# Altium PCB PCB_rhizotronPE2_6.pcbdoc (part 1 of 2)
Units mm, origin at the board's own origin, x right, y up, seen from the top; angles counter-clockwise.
Board outline 141.81 x 99.53 mm, 2 copper layers (Top Layer, Bottom Layer); 83 components, 239 nets, 496 pads, 263 vias.
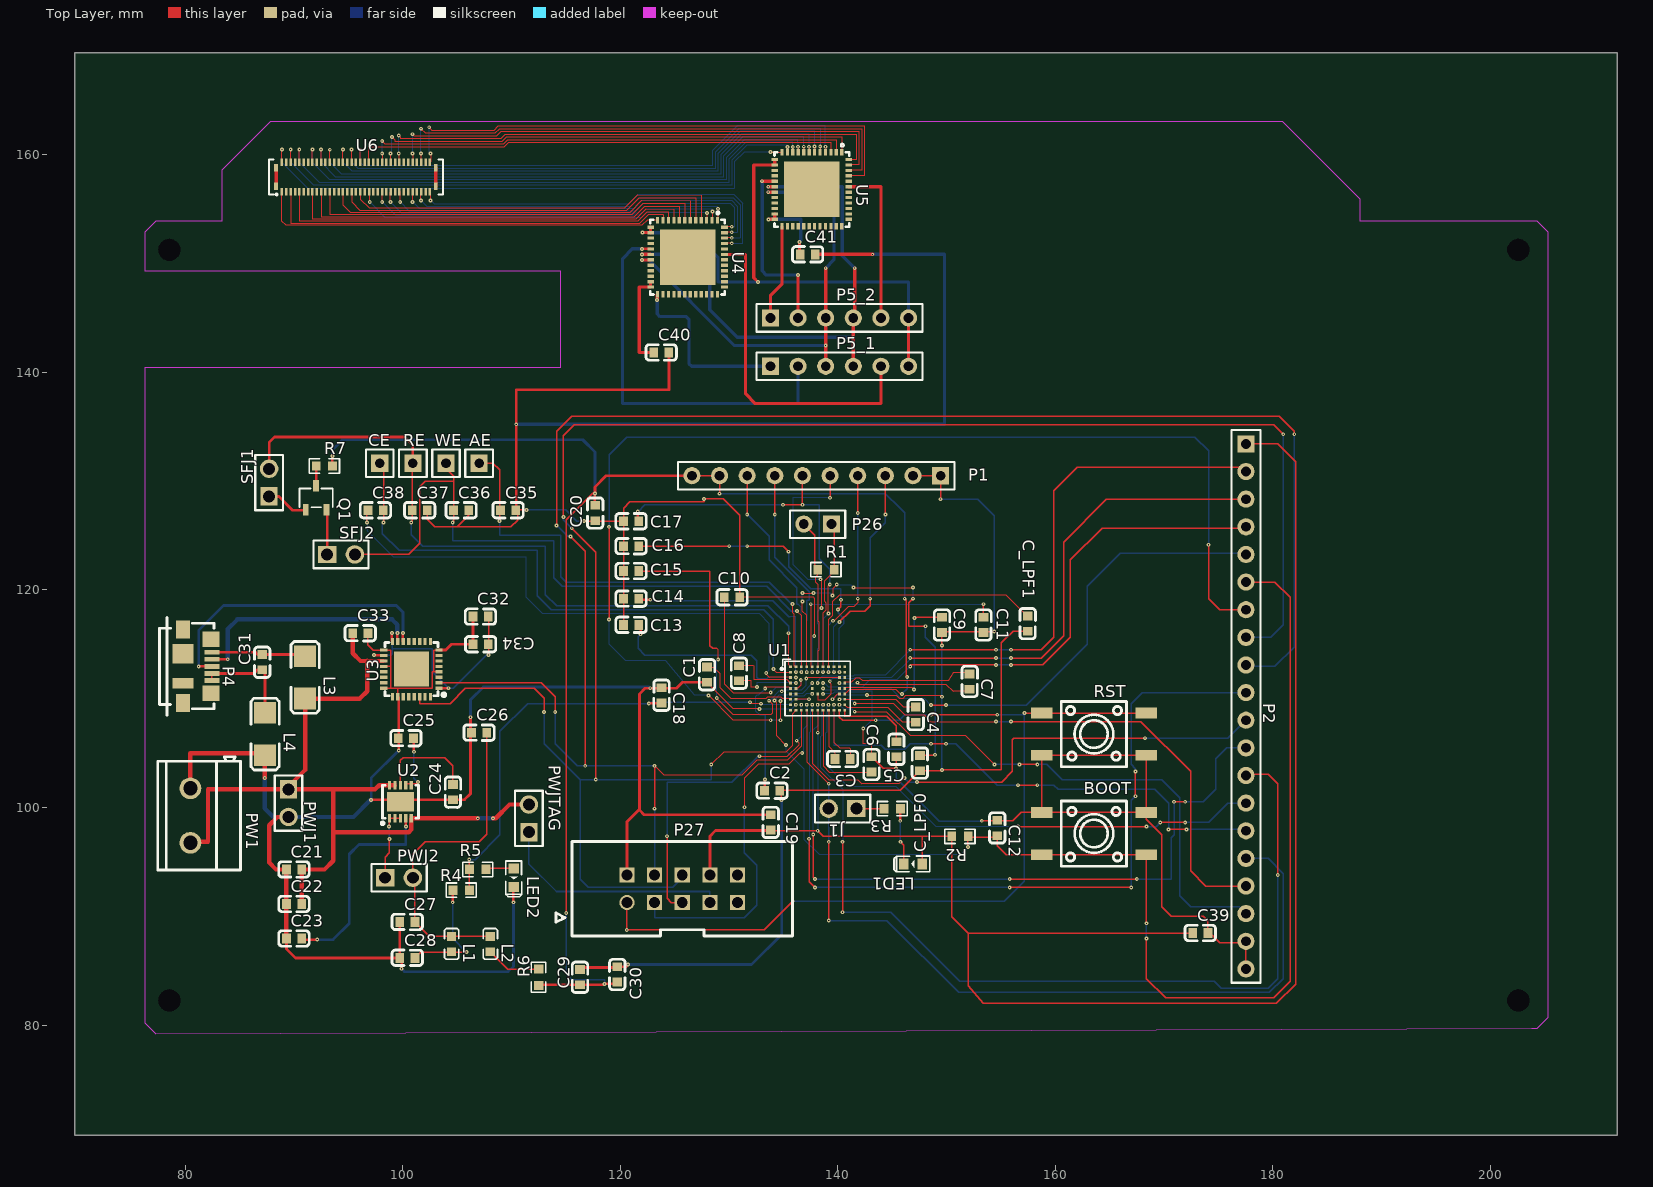
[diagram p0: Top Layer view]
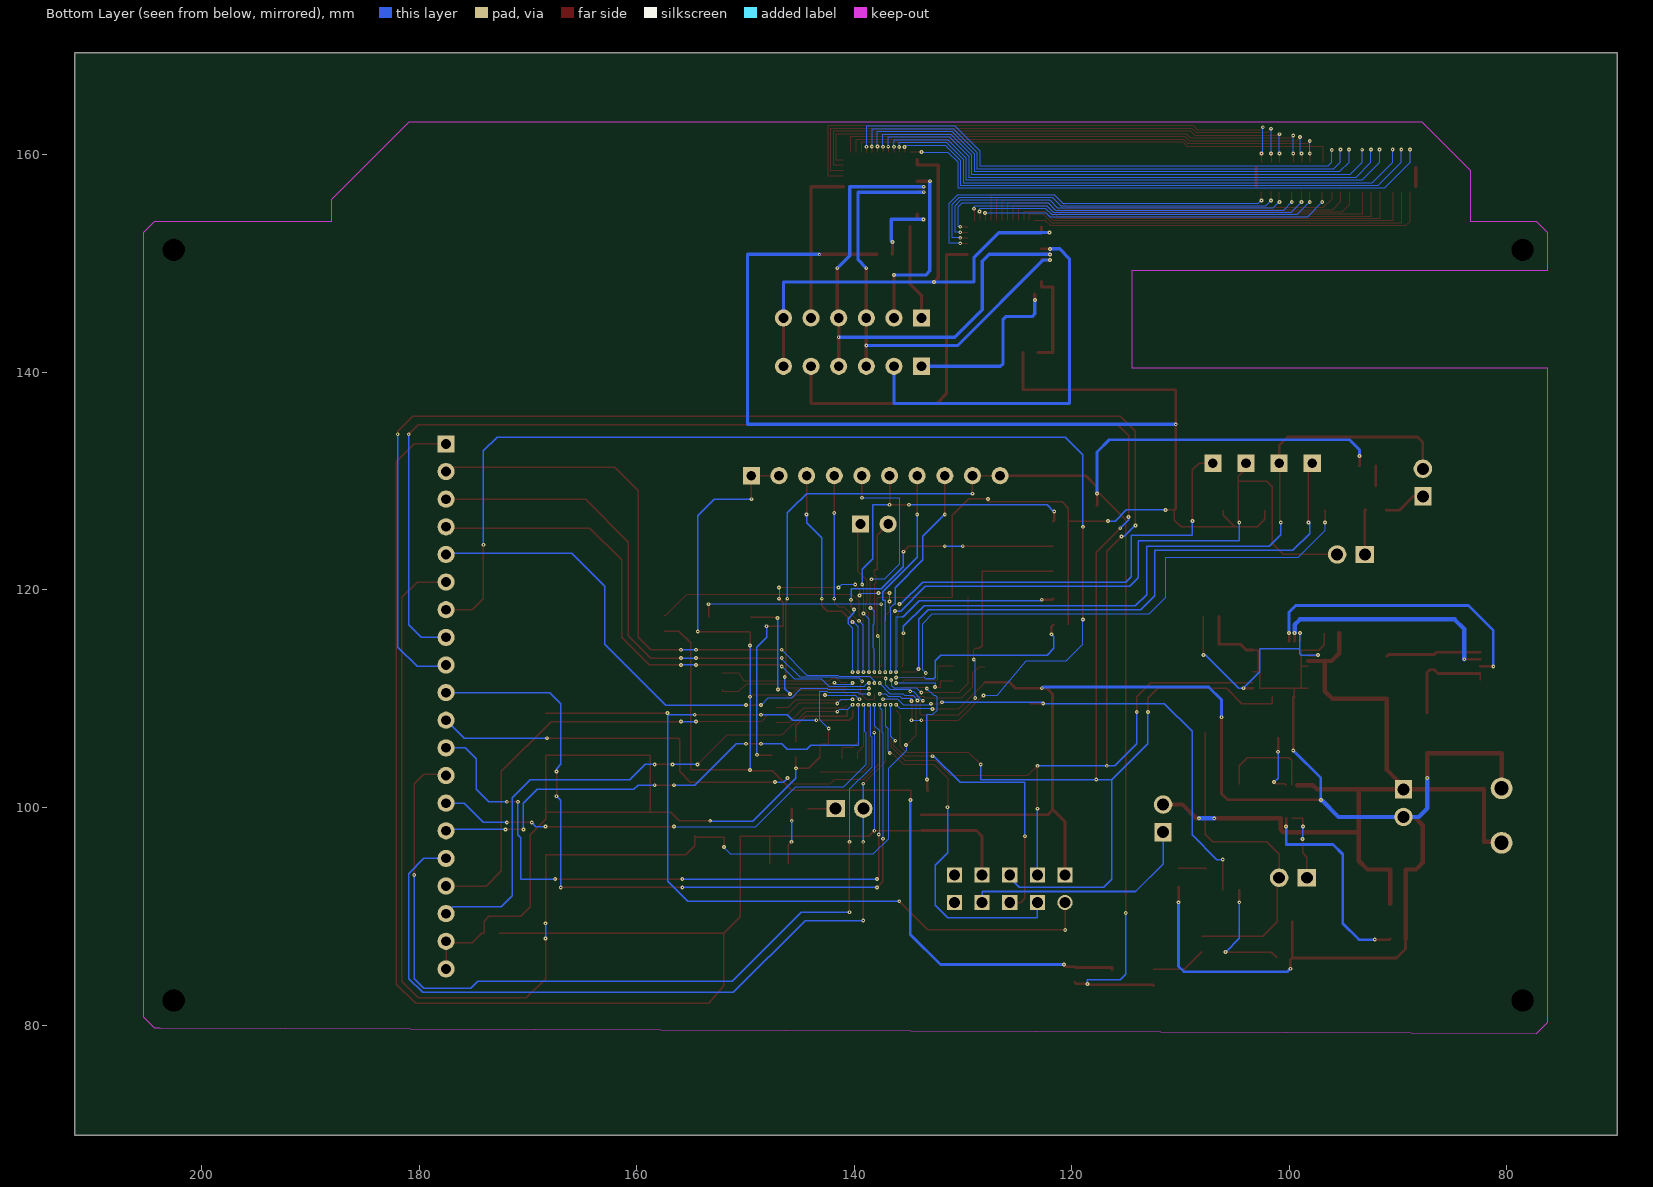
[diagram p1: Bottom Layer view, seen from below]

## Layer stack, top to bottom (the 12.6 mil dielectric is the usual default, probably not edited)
Top Layer: signal copper (thickness not stored)
Dielectric: dielectric 0.32, FR-4, Dk 4.8
Bottom Layer: signal copper (thickness not stored)

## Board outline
211.657,69.85 69.85,69.85 69.85,169.382 211.657,169.382
cut-out: 79.577,82.26 ccw(c78.561,82.26) 77.545,82.26 ccw(c78.561,82.26)
cut-out: 79.577,151.26 ccw(c78.561,151.26) 77.545,151.26 ccw(c78.561,151.26)
cut-out: 203.577,151.26 ccw(c202.561,151.26) 201.545,151.26 ccw(c202.561,151.26)
cut-out: 203.577,82.26 ccw(c202.561,82.26) 201.545,82.26 ccw(c202.561,82.26)

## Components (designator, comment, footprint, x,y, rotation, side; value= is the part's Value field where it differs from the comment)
AE "HDR-M-2.54_1x1" HDR-M-2.54_1X1 107.033,131.639 r270 top
BOOT "K4-6×6_SMD" KEY-SMD_4P-L6.0-W6.0-P3.90-LS10.0 163.548,97.603 r180 top
C1 "0.47uF" C0603 127.988,112.208 r90 top
C2 "0.47uF" C0603 133.957,101.54 r0 top
C3 "0.1uF" C0603 140.434,104.461 r180 top
C4 "0.1uF" C0603 147.165,108.525 r270 top
C5 "0.47uF" C0603 145.387,105.35 r90 top
C6 "0.47uF" C0603 143.101,103.953 r90 top
C7 "0.1uF" C0603 152.118,111.573 r270 top
C8 "0.1uF" C0603 130.909,112.335 r270 top
C9 "0.47uF" C0603 149.578,116.78 r90 top
C10 "0.47uF" C0603 130.274,119.32 r180 top
C11 "4.7uF" C0603 153.388,116.78 r90 top
C12 "0.1uF" C0603 154.658,98.111 r270 top
C13 "0.1uF" C0603 121.003,116.78 r0 top
C14 "0.1uF" C0603 121.003,119.193 r0 top
C15 "0.1uF" C0603 121.003,121.733 r0 top
C16 "0.1uF" C0603 121.003,124.019 r0 top
C17 "0.1uF" C0603 121.003,126.305 r0 top
C18 "0.1uF" C0603 123.797,110.303 r270 top
C19 "0.1uF" C0603 133.83,98.619 r270 top
C20 "0.1uF" C0603 117.701,127.067 r90 top
C21 "0.1uF" C0603 90.015,94.301 r0 top
C22 "10uF" C0603 90.015,91.126 r0 top
C23 "1uF" C0603 90.015,87.951 r0 top
C24 "1uF" C0603 104.62,101.413 r90 top
C25 "1uF" C0603 100.302,106.366 r0 top
C26 "10uF" C0603 107.033,106.874 r0 top
C27 "0.1uF" C0603 100.429,89.475 r0 top
C28 "0.1uF" C0603 100.429,86.173 r0 top
C29 "0.1uF" C0603 116.304,84.395 r90 top
C30 "10uF" C0603 119.733,84.649 r90 top
C31 "0.1uF" C0603 87.094,113.351 r90 top
C32 "0.1uF" C0603 107.16,117.542 r0 top
C33 "0.1uF" C0603 96.111,116.018 r0 top
C34 "0.1uF" C0603 107.16,115.002 r180 top
C35 "0.1uF" C0603 109.7,127.321 r0 top
C36 "0.1uF" C0603 105.382,127.321 r0 top
C37 "0.1uF" C0603 101.572,127.321 r0 top
C38 "0.1uF" C0603 97.508,127.321 r0 top
C39 "0.1uF" C0603 173.327,88.459 r0 top
C40 "0.1uF" C0603 123.773,141.823 r0 top
C41 "0.1uF" C0603 137.235,150.84 r0 top
C_LPF0 "4.7uF" C0603 147.546,104.08 r90 top
C_LPF1 "4.7uF" C0603 157.452,116.907 r90 top
CE "HDR-M-2.54_1x1" HDR-M-2.54_1X1 97.889,131.639 r270 top
J1 "HDR-M-2.54_1x2" HDR-M-2.54_1X2 140.434,99.889 r180 top
L1 "60Ω" L0603 104.493,87.443 r270 top
L2 "60Ω" L0603 108.049,87.443 r270 top
L3 "80Ω" L1806 91.031,111.954 r270 top
L4 "80Ω" L1806 87.348,106.747 r270 top
LED1 "LED-0603_G" LED0603_GREEN 146.911,94.809 r180 top
LED2 "LED-0603_G" LED0603_GREEN 110.208,93.539 r270 top
P1 "HDR-F-2.54_1x10" HDR-F-2.54_1X10 138.021,130.496 r180 top
P2 "HDR-F-2.54_1x20" HDR-F-2.54_1X20 177.518,109.287 r270 top
P4 "Micro B USB 2.0 SMD connector" SD-47346-001 83.157,112.97 r270 top
P5_1 "HDR-F-2.54_1x6" HDR-F-2.54_1X6 138.886,140.553 r0 top
P5_2 "HDR-F-2.54_1x6" HDR-F-2.54_1X6 138.886,144.998 r0 top
P26 "P26" HDR-F-2.54_1X2 138.148,126.051 r180 top
P27 "CONNMOLEX 2X5 Male" JTAG-10PIN-2.54MM-PTH 125.702,92.523 r0 top
PW1 "CONN-TH_2P-P5.00" CONN-TH_2P-P5.00 80.49,99.254 r270 top
PWJ1 "HDR-M-2.54_1x2" HDR-M-2.54_1X2 89.507,100.397 r270 top
PWJ2 "HDR-M-2.54_1x2" HDR-M-2.54_1X2 99.667,93.539 r0 top
PWJTAG "HDR-M-2.54_1x2" HDR-M-2.54_1X2 111.605,99 r90 top
Q1 "MMBFJ177" SOT-23-3_L3.0-W1.7-P0.95-LS2.9-BR 92.047,128.464 r270 top
R1 "200" R0603 138.91,121.86 r0 top
R2 "100K" R0603 151.229,97.349 r180 top
R3 "560" R0603 145.006,99.889 r180 top
R4 "2.2" R0603 105.382,92.396 r180 top
R5 "560" R0603 106.906,94.301 r180 top
R6 "2.2" R0603 112.494,84.395 r90 top
R7 "150K" R0603 92.809,131.385 r0 top
RE "HDR-M-2.54_1x1" HDR-M-2.54_1X1 100.937,131.639 r270 top
RST "K4-6×6_SMD" KEY-SMD_4P-L6.0-W6.0-P3.90-LS10.0 163.548,106.747 r0 top
SFJ1 "HDR-M-2.54_1x2" HDR-M-2.54_1X2 87.729,129.861 r90 top
SFJ2 "HDR-M-2.54_1x2" HDR-M-2.54_1X2 94.333,123.257 r0 top
U1 "ADUCM355BCCZ" lga-72_l6.0-w5.0-tl_aducm355bccz-rl7 138.148,110.938 r0 top
U2 "ADP7158ACPZ-3.3-R7" LFCSP-10_L3.0-W3.0-P0.50-BL-EP 99.794,100.524 r0 top
U3 "FT232RQ" QFN-32_L5.0-W5.0-P0.50-BL-EP 100.81,112.716 r90 top
U4 "ADG731BCPZ" LFCSP-48_L7.0-W7.0-P0.50-TL-EP5.1 126.186,150.586 r270 top
U5 "ADG731BCPZ" LFCSP-48_L7.0-W7.0-P0.50-TL-EP5.1 137.616,156.809 r270 top
U6 "DF40GB-70DP-0.4V(51)" "HIROSE DF40GB-70DP-0.4V(51)" 95.706,157.952 r0 top
WE "HDR-M-2.54_1x1" HDR-M-2.54_1X1 103.985,131.639 r270 top

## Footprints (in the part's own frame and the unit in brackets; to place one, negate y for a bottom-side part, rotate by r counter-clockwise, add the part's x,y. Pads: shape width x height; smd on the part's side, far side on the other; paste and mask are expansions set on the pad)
C0603 [mm]
  rect 0.8x0.9 smd paste+0 mask+0.051: 1(-0.7,0) 2(0.7,0)
  silkscreen extent -1.41,-0.71 1.39,0.72
CONN-TH_2P-P5.00 [mm]
  round 2 hole 1.3 paste+0 mask+0.051: 1(-2.504,0) 2(2.504,0)
  silkscreen extent -5.4,-3 5,4.6
HDR-F-2.54_1X2 [mil]
  rect 62x62 hole 35 paste+0 mask+2: 1(-50,0)
  round 62 hole 35 paste+0 mask+2: 2(50,0)
  silkscreen extent -100,-49 100,50
HDR-F-2.54_1X6 [mil]
  rect 62x62 hole 35 paste+0 mask+2: 1(-200,0)
  round 62 hole 35 paste+0 mask+2: 2(-100,0) 3(0,0) 4(100,0) 5(200,0) 6(300,0)
  silkscreen extent -250,-50 350,50
HDR-F-2.54_1X10 [mil]
  rect 62x62 hole 35 paste+0 mask+2: 1(-450,0)
  round 62 hole 35 paste+0 mask+2: 2(-350,0) 3(-250,0) 4(-150,0) 5(-50,0) 6(50,0) 7(150,0) 8(250,0) 9(350,0) 10(450,0)
  silkscreen extent -500,-50 500,50
HDR-F-2.54_1X20 [mil]
  rect 62x62 hole 35 paste+0 mask+2: 1(-950,0)
  round 62 hole 35 paste+0 mask+2: 2(-850,0) 3(-750,0) 4(-650,0) 5(-550,0) 6(-450,0) 7(-350,0) 8(-250,0) 9(-150,0) 10(-50,0) 11(50,0) 12(150,0) 13(250,0) 14(350,0) 15(450,0) 16(550,0) 17(650,0) 18(750,0) 19(850,0) 20(950,0)
  silkscreen extent -1000,-53 1000,53
HDR-M-2.54_1X1 [mil]
  rect 62x62 hole 35 paste+0 mask+2: 1(0,0)
  silkscreen extent -50,-50 50,50
HDR-M-2.54_1X2 [mm]
  rect 1.7x1.575 hole 1.1 paste+0 mask+0.051: 1(-1.27,0)
  round 1.7 hole 1.1 paste+0 mask+0.051: 2(1.27,0)
  silkscreen extent -2.54,-1.27 2.54,1.27
"HIROSE DF40GB-70DP-0.4V(51)" [mm]
  rect 0.23x0.66 smd paste+0 mask+0.051: 1(-6.8,-1.355) 2(-6.8,1.355) 3(-6.401,-1.355) 4(-6.4,1.355) 5(-6,-1.355) 6(-6,1.355) 7(-5.6,-1.355) 8(-5.6,1.355) 9(-5.2,-1.355) 10(-5.2,1.355) 11(-4.8,-1.355) 12(-4.8,1.355) 13(-4.4,-1.355) 14(-4.4,1.355) 15(-4,-1.355) 16(-4,1.355) 17(-3.6,-1.355) 18(-3.6,1.355) 19(-3.2,-1.355) 20(-3.2,1.355) 21(-2.8,-1.355) 22(-2.8,1.355) 23(-2.4,-1.355) 24(-2.4,1.355) 25(-2,-1.355) 26(-2,1.355) 27(-1.6,-1.355) 28(-1.6,1.355) 29(-1.2,-1.355) 30(-1.2,1.355) 31(-0.8,-1.355) 32(-0.8,1.355) 33(-0.4,-1.355) 34(-0.4,1.355) 35(0,-1.355) 36(0,1.355) 37(0.4,-1.355) 38(0.4,1.355) 39(0.8,-1.355) 40(0.8,1.355) 41(1.2,-1.355) 42(1.2,1.355) 43(1.6,-1.355) 44(1.6,1.355) 45(2,-1.355) 46(2,1.355) 47(2.4,-1.355) 48(2.4,1.355) 49(2.8,-1.355) 50(2.8,1.355) 51(3.2,-1.355) 52(3.2,1.355) 53(3.6,-1.355) 54(3.6,1.355) 55(4,-1.355) 56(4,1.355) 57(4.4,-1.355) 58(4.4,1.355) 59(4.8,-1.355) 60(4.8,1.355) 61(5.2,-1.355) 62(5.2,1.355) 63(5.6,-1.355) 64(5.6,1.355) 65(6,-1.355) 66(6,1.355) 67(6.4,-1.355) 68(6.4,1.355) 69(6.8,-1.355) 70(6.8,1.355)
  rect 0.35x0.7 smd paste+0 mask+0.051: 71(7.335,-0.86) 72(7.335,0.86) 73(-7.335,-0.86) SHLD(-7.335,0.86)
  silkscreen extent -8,-1.7 8,1.6
JTAG-10PIN-2.54MM-PTH [mm]
  round 1.4 hole 1.001 paste+0 mask+0.051: 1(-5.08,-1.27)
  rect 1.4x1.4 hole 1.001 paste+0 mask+0.051: 2(-5.08,1.27) 3(-2.54,-1.27) 4(-2.54,1.27) 5(0,-1.27) 6(0,1.27) 7(2.54,-1.27) 8(2.54,1.27) 9(5.08,-1.27) 10(5.08,1.27)
  silkscreen extent -11.61,-4.34 10.13,4.34
KEY-SMD_4P-L6.0-W6.0-P3.90-LS10.0 [mm]
  rect 2x1 smd paste+0 mask+0.051: 1(-4.8,1.95) 2(4.8,1.95) 3(-4.8,-1.95) 4(4.8,-1.95)
  silkscreen extent -3,-3 3,3
L0603 [mm]
  rect 0.8x0.864 smd paste-100 mask+0.051: 1(-0.7,0) 2(0.7,0)
  silkscreen extent -1.42,-0.65 1.41,0.67
L1806 [mm]
  rect 2x2 smd paste+0 mask+0.051: 1(-1.95,0) 2(1.95,0)
  silkscreen extent -3.3,-1.3 3.3,1.3
LED0603_GREEN [mm]
  rect 0.9x1 smd paste+0 mask+0.051: 1(-0.85,0) 2(0.85,0)
  silkscreen extent -1.54,-0.73 1.75,0.73
LFCSP-10_L3.0-W3.0-P0.50-BL-EP [mm]
  rect 0.3x0.8 smd paste+0 mask+0.051: 1(-1,-1.524) 2(-0.5,-1.524) 3(0,-1.524) 4(0.5,-1.524) 5(1,-1.524) 6(1,1.524) 7(0.5,1.524) 8(0,1.524) 9(-0.5,1.524) 10(-1,1.524)
  rect 2.5x1.75 smd paste+0 mask+0.051: 11(0,0)
  silkscreen extent -1.77,-2.11 1.65,1.52
LFCSP-48_L7.0-W7.0-P0.50-TL-EP5.1 [mm]
  rect 0.6x0.3 smd paste-100 mask+0.051: 1(-3.4,2.75) 2(-3.4,2.25) 3(-3.4,1.75) 4(-3.4,1.25) 5(-3.4,0.75) 6(-3.4,0.25) 7(-3.4,-0.25) 8(-3.4,-0.75) 9(-3.4,-1.25) 10(-3.4,-1.75) 11(-3.4,-2.25) 12(-3.4,-2.75) 25(3.4,-2.75) 26(3.4,-2.25) 27(3.4,-1.75) 28(3.4,-1.25) 29(3.4,-0.75) 30(3.4,-0.25) 31(3.4,0.25) 32(3.4,0.75) 33(3.4,1.25) 34(3.4,1.75) 35(3.4,2.25) 36(3.4,2.75)
  rect 0.3x0.6 smd paste-100 mask+0.051: 13(-2.75,-3.4) 14(-2.25,-3.4) 15(-1.75,-3.4) 16(-1.25,-3.4) 17(-0.75,-3.4) 18(-0.25,-3.4) 19(0.25,-3.4) 20(0.75,-3.4) 21(1.25,-3.4) 22(1.75,-3.4) 23(2.25,-3.4) 24(2.75,-3.4) 37(2.75,3.4) 38(2.25,3.4) 39(1.75,3.4) 40(1.25,3.4) 41(0.75,3.4) 42(0.25,3.4) 43(-0.25,3.4) 44(-0.75,3.4) 45(-1.25,3.4) 46(-1.75,3.4) 47(-2.25,3.4) 48(-2.75,3.4)
  rect 5.1x5.1 smd paste-100 mask+0.051: 49(0,0)
  silkscreen extent -4.19,-3.43 3.43,3.43
lga-72_l6.0-w5.0-tl_aducm355bccz-rl7 [mm]
  rect 0.25x0.25 smd paste+0 mask+0.051: A1(-2.5,2) A2(-2,2) A3(-1.5,2) A4(-1,2) A5(-0.5,2) A6(0,2) A7(0.5,2) A8(1,2) A9(1.5,2) A10(2,2) A11(2.5,2) B1(-2.5,1.5) B11(2.5,1.5) C1(-2.5,1) C10(2,1) C11(2.5,1) D1(-2.5,0.5) D11(2.5,0.5) E1(-2.5,0) E2(-2,0) E5(-0.5,0) E10(2,0) E11(2.5,0) F1(-2.5,-0.5) F2(-2,-0.5) F6(0,-0.5) F10(2,-0.5) F11(2.5,-0.5) G1(-2.5,-1) G2(-2,-1) G11(2.5,-1) H1(-2.5,-1.5) H11(2.5,-1.5) J1(-2.5,-2) J2(-2,-2) J3(-1.5,-2) J4(-1,-2) J5(-0.5,-2) J6(0,-2) J7(0.5,-2) J8(1,-2) J9(1.5,-2) J10(2,-2) J11(2.5,-2)
  round 0.35 hole 0.1 paste+0 mask+0.051: B2(-2,1.5) B3(-1.5,1.5) B4(-1,1.5) B5(-0.5,1.5) B6(0,1.5) B7(0.5,1.5) B8(1,1.5) B9(1.5,1.5) B10(2,1.5) C2(-2,1) D2(-2,0.5) D5(-0.5,0.5) D6(0,0.5) D7(0.5,0.5) D10(2,0.5) E7(0.5,0) F5(-0.5,-0.5) F7(0.5,-0.5) G10(2,-1) H2(-2,-1.5) H3(-1.5,-1.5) H4(-1,-1.5) H5(-0.5,-1.5) H6(0,-1.5) H7(0.5,-1.5) H8(1,-1.5) H9(1.5,-1.5) H10(2,-1.5)
  silkscreen extent -3.4,-2.5 3,2.7
QFN-32_L5.0-W5.0-P0.50-BL-EP [mil]
  rect 11.8x26 smd paste-3937 mask+1.97: 1(-68.9,-100) 2(-49.21,-100) 3(-29.53,-100) 4(-9.84,-100) 5(9.84,-100) 6(29.53,-100) 7(49.21,-100) 8(68.9,-100) 17(68.9,100) 18(49.21,100) 19(29.53,100) 20(9.84,100) 21(-9.84,100) 22(-29.53,100) 23(-49.21,100) 24(-68.9,100)
  rect 26x11.8 smd paste-3937 mask+1.97: 9(100,-68.9) 10(100,-49.21) 11(100,-29.53) 12(100,-9.84) 13(100,9.84) 14(100,29.53) 15(100,49.21) 16(100,68.9) 25(-100,68.9) 26(-100,49.21) 27(-100,29.53) 28(-100,9.84) 29(-100,-9.84) 30(-100,-29.53) 31(-100,-49.21) 32(-100,-68.9)
  rect 126x126 smd paste-3937 mask+1.97: 33(0,0)
  silkscreen extent -99,-123 96,96
R0603 [mm]
  rect 0.806x0.864 smd paste-100 mask+0.051: 1(-0.753,0) 2(0.753,0)
  silkscreen extent -1.39,-0.66 1.39,0.66
SD-47346-001 [mm]
  rect 0.45x1.38 smd paste+0 mask+0.102: 1(-1.3,-0.69) 2(-0.65,-0.69) 3(0,-0.69) 4(0.65,-0.69) 5(1.3,-0.69)
  rect 1.425x1.55 smd paste+0 mask+0.102: 6(-2.488,-0.775) GND(2.488,-0.775)
  rect 1.65x1.3 smd paste+0 mask+0.102: 7(-3.375,-3.35) 10(3.375,-3.35)
  rect 1.8x1.9 smd paste+0 mask+0.102: 8(-1.15,-3.35)
  rect 1x1.9 smd paste+0 mask+0.102: 9(1.55,-3.35)
  silkscreen extent -4.49,-5.5 4.49,-0.5
SOT-23-3_L3.0-W1.7-P0.95-LS2.9-BR [mm]
  rect 1.037x0.532 smd paste+0 mask+0.051: 1(1.101,-0.95) 2(1.101,0.95) 3(-1.101,0)
  silkscreen extent -0.86,-1.53 0.86,1.53

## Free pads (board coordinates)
  round 0.225 hole 0.1 paste+0 mask+0.051: 1(143.204,150.84)
  round 0.325 hole 0.1 paste+0 mask+0.051: 24(133.679,109.819)

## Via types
v1: diameter 0.35, hole 0.1, Top Layer to Bottom Layer, 263 vias

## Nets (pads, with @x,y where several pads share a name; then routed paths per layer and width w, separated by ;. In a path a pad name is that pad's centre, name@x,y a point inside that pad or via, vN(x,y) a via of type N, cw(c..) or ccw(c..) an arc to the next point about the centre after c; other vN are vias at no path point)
3V3VOUT: C32.2 C34.1 U3.1 U3.16 U3.18 | length 22.7
  Top Layer w0.125: C32.2@107.86,117.542 107.898,117.504 v1(107.898,114.01)
  Top Layer w0.225: v1(97.357,114.01) 98.226,114.01 U3.18@98.27,113.966 ; v1(99.008,116.042) 99.008,115.308 U3.16@99.06,115.256 ; U3.1@103.35,110.966 103.354,110.962 v1(104.215,110.962)
  Bottom Layer w0.125: v1(97.357,114.01) 98.907,114.01 99.032,114.135 99.032,114.596 ; v1(99.008,116.042) 99.032,116.018 99.032,114.596 ; v1(107.898,114.01) 107.692,114.01 104.644,110.962 v1(104.215,110.962) 102.715,112.462 102.715,114.596 99.032,114.596
5VUSB: C21.2 C22.2 C33.1 L3.2 PW1.2 PWJ1.1 PWJTAG.2 U2.5 U2.9 U2.10 U3.19 | length 79.2
  Top Layer w0.4: PW1.2@80.49,96.749 80.581,96.841 82.105,96.841 82.105,101.667 PWJ1.1@89.507,101.667 89.507,101.921 91.031,103.445 L3.2@91.031,110.004 96.065,110.003 96.746,110.684 96.746,112.97 96.746,113.478 U3.19@98.27,113.465 ; PWJ1.1@89.507,101.667 93.612,101.666 ; C22.2@90.715,91.126 C21.2@90.715,94.301 92.809,94.301 93.612,95.104 93.612,97.73 ; C33.1@95.411,116.018 95.41,114.174 96.121,113.465 96.746,113.465 ; U2.10@98.794,102.048 U2.9@99.294,102.048 ; U2.10@98.795,102.047 97.84,102.047 97.459,101.666 93.612,101.666 ; v1(106.906,99) U2.5@100.794,99 100.795,97.969 100.556,97.73 93.612,97.73 ; v1(108.303,99) 108.557,99 109.827,100.27 PWJTAG.2@111.605,100.27 ; 93.612,97.73 93.612,101.666
  Bottom Layer w0.4: v1(106.906,99) v1(108.303,99)
AFEDIE_GPIO0: P2.17 U1.G10 | length 49.8
  Top Layer w0.1: v1@141.553,109.565 145.109,109.565 146.149,108.525 147.927,108.525 148.562,107.89 v1(154.531,107.89)
  Top Layer w0.125: v1(155.928,107.89) 167.866,107.89 172.438,103.318 172.438,94.174 173.835,92.777 P2.17@177.518,92.777
  Bottom Layer w0.1: U1.G10@140.148,109.938 141.18,109.938 v1@141.553,109.565
  Bottom Layer w0.125: v1(154.531,107.89) v1(155.928,107.89)
  other v1: 141.553,109.565
AFEDIE_GPIO1: P2.18 U1.H10 | length 50.6
  Top Layer w0.1: v1@141.553,108.803 144.474,108.803 146.657,106.62 151.737,106.62 v1(154.404,103.953)
  Top Layer w0.125: v1(156.69,103.953) v1(158.341,103.953)
  Bottom Layer w0.1: U1.H10@140.148,109.438 140.581,109.006 141.35,109.006 v1@141.553,108.803
  Bottom Layer w0.125: v1(154.404,103.953) v1(156.69,103.953) ; v1(158.341,103.953) 159.23,103.953 160.627,102.556 169.771,102.556 171.422,100.905 171.422,91.888 172.438,90.872 176.883,90.872 P2.18@177.518,90.237
  other v1: 141.553,108.803
AGND: C2.2 C9.1 C10.1 C11.1 C13.1 C14.1 C15.1 C16.1 C17.1 C20.1 C29.2 C30.2 C35.2 C36.2 C37.2 C40.2 C41.2 C_LPF0.1 C_LPF1.1 P1.1 P1.2 pad.1 U1.B5 U1.F10 | length 280.7
  Top Layer w0.1: C10.1@130.974,119.32 137.767,119.32 137.894,119.193 137.894,115.822 v1(137.837,115.764) ; v1(139.521,109.946) 140.013,110.438 U1.F10@140.148,110.438 ; v1(142.696,110.327) 142.72,110.303 145.387,110.303 145.641,110.049 146.001,110.049 146.256,110.303 149.578,110.303 v1(149.578,110.176)
  Top Layer w0.125: C37.2@102.272,127.321 102.272,126.494 102.969,125.797 105.001,125.797 ; C36.2@106.082,127.321 106.082,126.878 105.001,125.797 ; v1(111.393,127.345) 110.566,127.345 110.566,126.409 109.954,125.797 105.001,125.797 ; v1(116.661,126.329) 116.685,126.305 C17.1@120.303,126.305 ; C13.1@120.303,116.78 C14.1@120.303,119.193 C15.1@120.303,121.733 C16.1@120.303,124.019 C17.1@120.303,126.305 ; C10.1@130.974,119.32 130.974,126.875 129.488,128.361 v1(127.71,128.361) 127.71,128.083 120.876,128.083 120.303,127.51 C17.1@120.303,126.305 ; v1@134.822,100.675 134.822,101.564 145.73,101.564 C_LPF0.1@147.546,103.38 149.513,103.38 v1(149.578,103.445) 155.039,103.445 155.039,115.129 156.117,116.207 C_LPF1.1@157.452,116.207 ; P1.2@146.911,130.496 P1.1@149.451,130.496 v1(149.451,128.337) ; v1(149.578,114.875) C9.1@149.578,116.08 149.667,116.169 v1@154.38,116.169
  Top Layer w0.254: C35.2@110.565,127.345 110.438,127.472 v1(110.438,135.219) 110.438,138.394 124.473,138.394 C40.2@124.473,141.823 ; C29.2@116.304,85.095 116.304,85.284 119.668,85.284 C30.2@119.733,85.349 120.512,85.349 v1(120.725,85.562)
  Top Layer w0.3: C41.2@137.935,150.84 142.845,150.84 pad.1@143.204,150.84
  Bottom Layer w0.1: U1.B5@137.648,112.438 137.648,115.575 v1(137.837,115.764) ; v1(139.521,109.946) 139.902,110.327 v1(142.696,110.327)
  Bottom Layer w0.125: v1(111.393,127.345) 115.01,127.345 116.026,126.329 v1(116.661,126.329) ; v1(149.451,128.337) 152.88,128.337 154.404,126.813 154.404,116.526 154.38,116.502 v1@154.38,116.169 ; v1(149.578,103.445) v1(149.578,110.176) v1(149.578,114.875)
  Bottom Layer w0.254: v1(120.725,85.562) 132.076,85.562 134.846,88.332 134.846,100.651 v1@134.822,100.675
  Bottom Layer w0.3: v1(110.438,135.219) 149.808,135.219 149.808,150.84 pad.1@143.204,150.84
  other v1: 134.822,100.675 154.38,116.169
AIN0: P1.3 U1.B9 | length 20.8
  Top Layer w0.125: v1@140.156,117.058 141.148,118.05 142.466,118.05 142.974,118.558 v1(142.974,119.193) ; v1(144.371,126.94) P1.3@144.371,130.496
  Bottom Layer w0.1: U1.B9@139.648,112.486 139.648,116.629 140.077,117.058 v1@140.156,117.058
  Bottom Layer w0.125: v1(142.974,119.193) 142.974,124.781 144.371,126.178 v1(144.371,126.94)
  other v1: 140.156,117.058
AIN1: P1.4 U1.B8 | length 19.5
  Top Layer w0.1: v1(139.545,117.161) 139.672,117.161 140.942,118.431 141.45,118.431 141.831,118.812 v1(141.831,119.193)
  Top Layer w0.125: v1(141.831,127.067) P1.4@141.831,130.496
  Bottom Layer w0.1: U1.B8@139.148,112.486 139.148,116.764 v1(139.545,117.161)
  Bottom Layer w0.125: v1(141.831,119.193) v1(141.831,127.067)
AIN2: P1.5 U1.B6 | length 23.5
  Top Layer w0.1: v1(138.411,120.971) 138.505,120.875 v1(138.505,118.328)
  Top Layer w0.125: v1(139.291,128.464) P1.5@139.291,130.496
  Bottom Layer w0.1: U1.B6@138.148,112.438 138.148,114.587 138.251,114.69 138.251,116.792 138.148,116.895 138.148,118.05 138.426,118.328 v1(138.505,118.328) ; v1@138.402,120.971 137.259,120.971 135.862,122.368 135.862,123.237 135.862,128.464 v1(139.291,128.464)
AIN3: C17.2 P1.6 U1.B7 | length 36.6
  Top Layer w0.1: v1@139.14,117.82 139.14,120.36 v1@139.267,120.487
  Top Layer w0.125: v1(134.973,127.829) v1(136.751,127.829) P1.6@136.751,130.496
  Top Layer w0.225: v1(121.614,127.218) 121.614,126.394 C17.2@121.703,126.305
  Bottom Layer w0.1: U1.B7@138.648,112.486 138.648,117.328 v1@139.14,117.82
  Bottom Layer w0.125: v1@121.615,127.217 121.638,127.194 122.273,127.829 v1(134.973,127.829) ; v1(136.751,127.829) 138.275,127.829 138.275,122.876 139.267,121.884 v1@139.267,120.487
  other v1: 139.14,117.82 139.267,120.487
AIN5: P1.7 U1.B4 | length 19.6
  Top Layer w0.125: v1(134.211,126.94) P1.7@134.211,130.496
  Bottom Layer w0.1: U1.B4@137.148,112.438 137.147,117.161
  Bottom Layer w0.125: v1(134.211,126.94) 134.211,123.003 137.386,119.828 137.386,119.066 137.132,119.066 137.132,117.161
AIN6: P1.8 U1.B3 | length 20.1
  Top Layer w0.125: v1(131.671,126.94) P1.8@131.671,130.496
  Bottom Layer w0.1: 136.37,118.685 136.648,118.407 U1.B3@136.648,112.486
  Bottom Layer w0.125: v1(131.671,126.94) 133.703,124.908 133.703,122.749 136.243,120.209 136.243,118.685 136.37,118.685
AVDD: C20.2 C29.1 C30.1 P1.9 P1.10 R6.1 R7.2 U1.F11 | length 142.7
  Top Layer w0.1: U1.F11@140.648,110.438 140.696,110.438 141.069,110.811 145.387,110.811 145.759,110.439 v1(145.895,110.439)
  Top Layer w0.125: v1@115.034,90.237 115.034,126.432 117.471,128.869 v1(117.677,128.869) ; P1.10@126.591,130.496 P1.9@129.131,130.496 v1(129.131,128.845) ; v1(146.149,119.193) 146.274,119.068 146.274,112.083 v1@146.379,111.978
  Top Layer w0.225: v1(93.547,132.298) 93.547,131.4 R7.2@93.562,131.385 ; v1(117.677,128.869) 117.677,127.791 C20.2@117.701,127.767 ; v1(118.566,83.784) 119.568,83.784 C30.1@119.733,83.949
  Top Layer w0.254: R6.1@112.494,83.642 112.547,83.695 C29.1@116.304,83.695 118.477,83.695 v1(118.566,83.784) ; v1(117.677,128.869) 117.677,129.456 118.717,130.496 P1.10@126.591,130.496
  Bottom Layer w0.125: v1(115.034,90.288) 115.034,84.649 115.542,84.141 118.566,84.141 v1(118.566,83.784) ; v1(129.131,128.845) 144.371,128.845 145.679,127.537 146.149,127.067 v1(146.149,119.193) ; v1@145.895,110.43 146.379,110.914 v1@146.379,111.978
  Bottom Layer w0.254: v1(93.547,132.298) 93.547,132.885 94.46,133.798 116.558,133.798 117.677,132.679 v1(117.677,128.869)
  other v1: 146.379,111.978
C23_2: C23.2 U2.4 | length 19.4
  Top Layer w0.225: C23.2@90.715,87.951 90.818,87.848 v1(92.15,87.848) ; v1(100.294,98.244) U2.4@100.294,99
  Bottom Layer w0.254: v1(92.15,87.848) 93.595,87.848 95.095,89.348 95.095,95.698 95.984,96.587 100.294,96.587 v1(100.294,98.244)
C24_2: C24.2 U2.8 | length 9.2
  Top Layer w0.125: U2.8@99.794,102.048 99.794,104.334 100.048,104.588 103.858,104.588 104.62,103.826 C24.2@104.62,102.113
C25_2: C25.2 U2.6 U2.7 | length 5.5
  Top Layer w0.125: U2.7@100.294,102.048 100.445,102.199 101.294,102.199 v1(101.421,102.326)
  Top Layer w0.225: C25.2@101.002,106.366 101.04,106.328 v1(101.04,105.12)
  Bottom Layer w0.125: v1(101.04,105.12) 101.04,102.707 v1(101.421,102.326)
CAP_POT0: C38.1 U1.C1 | length 51.7
  Top Layer w0.1: v1(133.425,112.359) 133.425,112.232 133.703,111.954 135.632,111.954 U1.C1@135.648,111.938
  Top Layer w0.125: v1(96.722,126.202) 96.722,127.235 C38.1@96.808,127.321
  Bottom Layer w0.1: v1(96.722,126.202) 96.746,126.178 96.746,125.416 99.159,123.003 111.351,123.003 111.351,119.32 112.875,117.796 132.814,117.796 133.703,116.907 133.703,112.637 v1(133.425,112.359)
CAP_POT1: U1.C11
CE0: C38.2 CE.1 U1.B1 | length 54.6
  Top Layer w0.1: v1(134.084,112.716) 134.338,112.439 U1.B1@135.648,112.438
  Top Layer w0.125: CE.1@97.889,131.639 98.246,131.282 v1(98.246,126.202)
  Bottom Layer w0.125: v1(98.246,126.202) 98.143,126.099 98.143,125.162 99.667,123.638 112.367,123.638 112.367,119.447 113.637,118.177 133.195,118.177 134.084,117.288 v1(134.084,112.716)
CE1: U1.B11
D1: P5_1.5 U4.43 | length 31
  Top Layer w0.3: U4.43@129.586,150.836 131.52,150.836 131.52,138.013 132.409,137.124 143.966,137.124 P5_1.5@143.966,140.553
D2: P5_2.5 U5.43 | length 15
  Top Layer w0.3: U5.43@141.016,157.059 143.966,157.059 P5_2.5@143.966,144.998
DE0: AE.1 C35.1 U1.A2 | length 45.8
  Top Layer w0.1: v1@135.852,118.685 135.852,117.875 135.979,117.748 ; 135.979,112.97 135.979,117.746 ; 135.989,112.97 U1.A2@136.116,112.97
  Top Layer w0.125: AE.1@107.033,131.639 108.3,131.639 108.914,131.025 v1(108.914,126.329)
  Bottom Layer w0.125: v1(108.914,126.329) 108.938,126.305 108.938,125.035 114.526,125.035 114.526,121.225 115.034,120.717 133.703,120.717 135.711,118.709 v1@135.838,118.709
  other v1: 135.838,118.709
DE1: U1.A10
DIN: P5_1.4 P5_2.4 U4.18 U5.18 | length 50.4
  Top Layer w0.3: v1(121.995,150.84) 122.782,150.84 U4.18@122.786,150.836 ; v1(133.608,157.059) U5.18@134.216,157.059 ; P5_1.4@141.426,140.553 v1(141.426,143.22) P5_2.4@141.426,144.998 141.553,145.125 v1(141.553,149.57)
  Bottom Layer w0.3: v1(121.995,150.84) 127.583,150.84 128.218,150.205 128.218,145.76 130.758,143.22 v1(141.426,143.22) ; v1(133.608,157.059) 140.41,157.059 140.41,150.713 v1(141.553,149.57)
DVDD: C18.2 C19.2 C39.1 LED1.1 P2.1 P27.8 R2.2 R4.1 R5.2 U1.F1 U1.G2 U1.J6 | length 208.1
  Top Layer w0.1: v1(131.925,109.668) 132.052,109.541 v1(132.941,109.541) ; U1.G2@136.148,109.938 136.156,109.946 v1(137.362,109.946) ; v1@138.148,106.874 U1.J6@138.148,108.938
  Top Layer w0.125: v1(106.12,95.214) 106.12,92.412 R4.1@106.135,92.396 ; C19.2@133.806,97.881 138.124,97.881 v1(138.148,97.857) 138.656,97.349 R2.2@150.476,97.349 150.476,89.974 151.991,88.459 ; LED1.1@147.761,94.809 147.761,97.349 ; C39.1@172.627,88.459 151.991,88.459 ; P2.1@177.518,133.417 180.439,133.417 182.09,131.766 182.09,83.76 180.312,81.982 153.388,81.982 151.991,83.633 151.991,88.459
  Top Layer w0.225: v1(122.63,109.565) 123.759,109.565 C18.2@123.797,109.603
  Top Layer w0.254: P27.8@128.242,93.793 128.242,97.349 128.774,97.881 C19.2@133.806,97.881
  Bottom Layer w0.1: v1@132.941,109.561 132.941,109.434 135.481,109.434 135.985,109.938 137.354,109.938 v1(137.362,109.946) ; v1(138.148,97.857) v1@138.148,106.874
  Bottom Layer w0.125: v1(106.12,95.214) 106.676,95.214 108.938,97.476 108.938,107.001 111.478,109.541 122.607,109.541 v1@122.63,109.564 ; v1(122.63,109.565) 122.733,109.668 v1(131.925,109.668)
  other v1: 138.157,106.874
GND: BOOT.3 BOOT.4 C1.1 C5.1 C6.2 C12.1 C18.1 C19.1 C21.1 C22.1 C23.1 C24.1 C25.1 C26.1 C27.1 C28.1 C32.1 C33.2 C34.2 C39.2 L4.2 LED2.2 P2.19 P2.20 P27.2 PW1.1 PWJ1.2 RST.3 RST.4 U1.F2 U1.F7 U1.H2 U2.11 U3.4 U3.8 U3.17 U3.20 U3.24 U3.26 | length 271.1
  Top Layer w0.1: C1.1@127.988,111.508 127.988,111.446 130.377,109.057 v1@132.79,109.057 ; v1(142.339,107.255) 142.339,105.858 142.974,105.858 143.101,105.731 C6.2@143.101,104.653
  Top Layer w0.125: C33.2@96.811,116.018 96.811,114.937 97.282,114.466 U3.17@98.27,114.466 98.905,114.466 98.905,112.965 ; U3.24@98.27,110.966 98.27,110.938 98.905,110.938 ; U3.20@98.27,112.965 98.9,112.965 98.905,110.938 ; 98.905,110.999 98.905,110.938 ; U3.26@99.56,110.176 99.56,110.938 ; 102.842,112.466 102.842,114.466 U3.8@103.35,114.466 ; U3.4@103.35,112.466 102.715,112.466 102.715,110.938 99.56,110.938 ; C6.2@143.101,104.653 144.158,103.596 145.363,103.596 145.387,103.62 C5.1@145.387,104.65 ; v1@153.237,98.77 156.079,98.77 156.862,99.553 BOOT.4@158.748,99.553 ; BOOT.3@168.348,99.553 168.348,98.898 169.771,97.476 169.771,90.872 170.66,89.983 173.583,89.983 174.028,89.541 C39.2@174.027,88.459 ; C39.2@174.027,88.459 174.216,88.459 175.105,87.57 177.391,87.57 P2.19@177.518,87.697 P2.20@177.518,85.157 ; 98.905,110.938 99.56,110.938 ; BOOT.4@158.748,99.553 RST.3@158.748,104.797 RST.4@168.348,104.797 BOOT.3@168.348,99.553 BOOT.4@158.748,99.553
  Top Layer w0.225: C28.1@99.729,86.173 99.905,85.997 v1(99.905,85.173) ; v1(110.184,91.277) 110.184,92.665 LED2.2@110.208,92.689
  Top Layer w0.254: C23.1@89.315,87.951 89.314,87.001 90.142,86.173 C28.1@99.729,86.173 ; v1(97.103,100.675) 97.141,100.713 C24.1@104.62,100.713 105.698,100.713 106.247,101.262 v1(106.247,108.295) ; U3.26@99.56,110.176 99.642,110.094 v1@99.642,105.247 ; C28.1@99.729,86.173 C27.1@99.729,89.475 ; U3.8@103.35,114.466 103.957,114.466 104.493,115.002 C34.2@106.46,115.002 C32.1@106.46,117.542 ; P27.2@120.622,93.793 120.622,98.688 121.765,99.831 ; v1@122.757,110.961 125.17,110.961 125.717,111.508 C1.1@127.988,111.508 ; v1(122.757,110.962) 122.297,110.962 121.765,110.43 121.765,99.762 122.207,99.32 C19.1@133.83,99.319
  Top Layer w0.4: PW1.1@80.49,101.758 80.49,104.993 87.324,104.993 v1(87.324,102.707) ; C23.1@89.315,87.951 C22.1@89.315,91.126 C21.1@89.315,94.301 88.364,94.301 87.729,94.936 87.729,98.365 88.491,99.127 PWJ1.2@89.507,99.127
  Bottom Layer w0.1: v1@132.79,109.057 135.767,109.057 U1.H2@136.148,109.438 ; U1.F7@138.648,110.438 138.664,110.454 139.521,110.454 139.66,110.593 142.422,110.593 142.522,110.693 143.163,110.693 143.163,108.079 v1(142.339,107.255)
  Bottom Layer w0.125: v1@145.363,103.596 145.363,102.707 149.324,98.746 153.213,98.746 v1@153.237,98.77
  Bottom Layer w0.254: v1(97.103,100.675) 97.103,102.708 v1@99.642,105.247 ; v1(99.905,85.173) 100.175,84.903 109.7,84.903 110.184,85.387 v1(110.184,91.277) ; v1(106.247,108.295) 106.247,109.898 107.414,111.065 122.654,111.065 v1(122.757,110.962)
  Bottom Layer w0.4: v1(87.324,102.707) 87.324,99.913 88.11,99.127 PWJ1.2@89.507,99.127 95.476,99.127 97.024,100.675 v1(97.103,100.675)
  other v1: 153.237,98.77 145.363,103.596 99.643,105.247 132.79,109.057
L1_2: C28.2 L1.2 R4.2 | length 11.2
  Top Layer w0.125: C28.2@101.129,86.173 101.661,86.705 v1(105.866,86.705)
  Top Layer w0.225: v1(104.596,91.277) 104.596,92.363 R4.2@104.629,92.396
  Bottom Layer w0.125: v1(104.596,91.277) 104.596,87.975 v1(105.866,86.705)
L2_2: L2.2 R6.2 | length 5.1
  Top Layer w0.125: L2.2@108.049,86.743 109.644,85.148 R6.2@112.494,85.148
LED1_2: LED1.2 R3.1 | length 5.2
  Top Layer w0.125: v1(145.768,96.841) 146.061,96.548 LED1.2@146.061,94.809
  Top Layer w0.225: v1(145.744,98.77) 145.744,99.874 R3.1@145.759,99.889
  Bottom Layer w0.125: v1@145.744,98.77 145.744,96.865 v1(145.768,96.841)
P0.0_SCLK0: P2.15 U1.H9 | length 46.7
  Top Layer w0.125: v1(148.562,105.858) v1(149.959,105.858) ; v1(156.563,102.048) v1(158.341,102.048) ; v1(170.406,97.984) v1(172.057,97.984)
  Bottom Layer w0.1: 139.648,105.731 U1.H9@139.648,109.438
  Bottom Layer w0.125: 139.648,105.731 143.99,105.731 144.371,105.35 146.149,105.35 146.657,105.858 v1(148.562,105.858) ; v1(149.959,105.858) 150.848,105.858 154.658,102.048 v1(156.563,102.048) ; v1(158.341,102.048) 159.865,102.048 160.246,101.667 169.136,101.667 170.406,100.397 v1(170.406,97.984) ; v1(172.057,97.984) 177.391,97.984 P2.15@177.518,97.857
P0.1_MOSI0: P2.14 U1.H8 | length 47.5
  Top Layer w0.125: v1(156.563,98.238) v1(168.374,98.238) ; v1(169.644,98.619) v1(171.93,98.619)
  Bottom Layer w0.1: U1.H8@139.148,109.438 139.013,109.303 139.013,106.977 138.91,106.874 138.91,103.953 140.942,101.921 145.387,101.921 149.07,98.238 v1(156.563,98.238)
  Bottom Layer w0.125: v1(168.374,98.238) 169.263,98.238 v1(169.644,98.619) ; v1(171.93,98.619) 174.089,98.619 175.867,100.397 P2.14@177.518,100.397
P0.2_MISO0: P2.13 U1.H7 | length 84.5
  Top Layer w0.125: v1(140.434,90.364) v1(140.434,96.841) ; P2.13@177.518,102.937 177.645,103.064 179.55,103.064 180.439,102.175 v1(180.439,93.793)
  Bottom Layer w0.1: U1.H7@138.648,109.438 138.505,109.295 138.505,106.596 138.402,106.493 138.402,103.699 140.434,101.667 v1(140.434,96.841)
  Bottom Layer w0.125: v1(140.434,90.364) 144.879,90.364 151.229,84.014 174.597,84.014 175.232,83.379 179.55,83.379 180.439,84.268 v1(180.439,93.793)
P0.3_CS0: P2.12 U1.H6 | length 66.6
  Top Layer w0.125: v1@137.743,97.5 137.743,93.563 v1(137.894,93.412) ; v1(155.801,93.412) v1(167.485,93.412) ; v1(170.914,100.524) v1(171.93,100.524)
  Bottom Layer w0.1: v1@137.743,97.5 137.716,97.527 137.716,107.077 138.148,107.509 U1.H6@138.148,109.438
  Bottom Layer w0.125: v1(137.894,93.412) v1(155.801,93.412) ; v1(167.485,93.412) 170.66,93.412 170.66,97.222 170.914,97.476 v1(170.914,100.524) ; v1(171.93,100.524) 173.581,100.524 174.724,101.667 174.724,104.461 175.74,105.477 P2.12@177.518,105.477
  other v1: 137.743,97.5
P0.4_SCL: P2.11 U1.J5 | length 50
  Top Layer w0.1: U1.J5@137.648,108.938 137.647,104.072 139.164,102.556 141.831,102.556 142.212,102.175 145.593,102.175 v1@146.125,102.707
  Top Layer w0.125: v1@147.268,102.326 155.063,102.326 156.055,103.318 156.055,106.239 156.182,106.366 v1(168.247,106.366)
  Bottom Layer w0.125: v1@146.125,102.707 146.506,102.326 v1@147.268,102.326 ; v1(168.247,106.366) 175.867,106.366 P2.11@177.518,108.017
  other v1: 147.268,102.326 146.125,102.707
P0.5_SDA: P2.10 U1.H5 | length 74.4
  Top Layer w0.125: v1@137.362,97.119 137.362,93.182 v1(137.894,92.65) ; v1(155.801,92.65) v1(166.977,92.65) ; v1(167.358,101.032) v1(167.358,103.318)
  Bottom Layer w0.1: v1@137.362,97.119 137.362,106.85 137.462,106.95 137.462,108.998 137.648,109.184 U1.H5@137.648,109.438
  Bottom Layer w0.125: v1(137.894,92.65) v1(155.801,92.65) ; v1(166.977,92.65) 166.977,100.651 v1(167.358,101.032) ; v1(167.358,103.318) 167.358,103.572 166.977,103.953 166.977,109.541 167.993,110.557 P2.10@177.518,110.557
  other v1: 137.362,97.119
P0.10_SOUT: P2.9 P27.4 U1.J3 U3.2 | length 179.8
  Top Layer w0.1: v1(123.162,103.826) 124.051,102.937 131.163,102.937 132.56,104.334 135.354,104.334 136.647,105.627 U1.J3@136.648,108.938
  Top Layer w0.125: U3.2@103.35,111.466 112.728,111.466 114.018,110.176 v1(114.018,108.779) ; v1(114.145,125.924) 114.145,134.56 115.542,135.957 180.566,135.957 181.963,134.56 v1(181.963,134.306) ; v1(115.415,124.908) 116.783,123.54 v1(116.783,103.826) ; v1(123.162,99.889) v1(123.162,103.826)
  Bottom Layer w0.125: v1(114.018,108.779) 114.018,105.858 116.05,103.826 v1(116.783,103.826) v1(123.162,103.826) ; v1(114.145,125.924) 115.161,124.908 v1(115.415,124.908) ; P27.4@123.162,93.793 v1(123.162,99.889) ; P2.9@177.518,113.097 177.645,112.97 180.185,112.97 181.963,114.748 v1(181.963,134.306)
